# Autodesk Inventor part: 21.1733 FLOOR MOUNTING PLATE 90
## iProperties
Created: 2007-04
Part Number: 21.1733 FLOOR MOUNTING PLATE 90
Material: Aluminum-6061
Document SubType Name: Modeling
Designer: Andy Moles
Density: 2.71 g/cm^3
Author: Andy Moles
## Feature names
1. Extrusion1
2. Extrusion2
